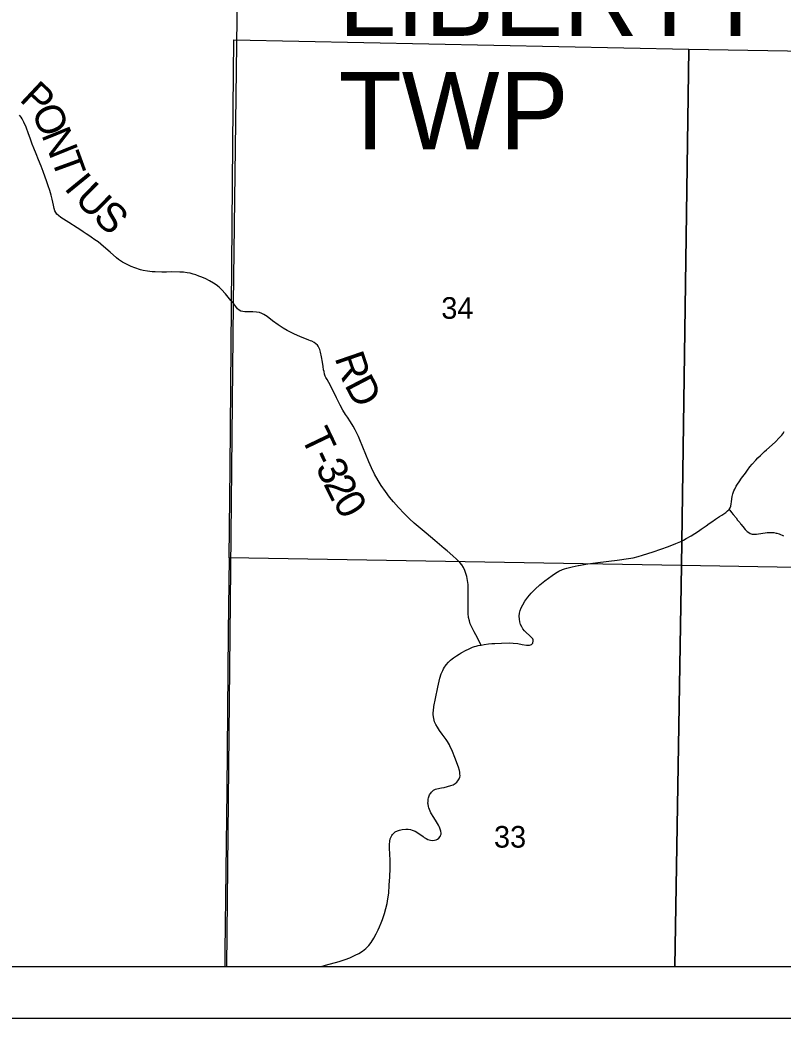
# Model space of a CAD drawing. Extents: x 0 to 34, y 0 to 22.
# Drawn here: x 6.032 to 7.51, y 14 to 15.933 of the extents above; entities that cross this region are included whole.
import ezdxf

# ---------------------------------------------------------------- set-up
doc = ezdxf.new("R2010")
doc.units = 0
for name, color, linetype in [('GM_X_Corporation', 7, 'Continuous'), ('GM_X_County_Road', 7, 'Continuous'), ('GM_X_Section_Text', 7, 'Continuous'), ('GM_X_Township_Road', 7, 'Continuous'), ('GM_X_Township_Road_Text', 7, 'Continuous'), ('GM_X_Township_Text', 7, 'Continuous'), ('SH_Data', 7, 'Continuous'), ('SH_Text', 7, 'Continuous')]:
    doc.layers.add(name, color=color, linetype=linetype)

msp = doc.modelspace()

# ---------------------------------------------------------------- linework, layer by layer
at = {"layer": 'GM_X_Corporation'}
msp.add_lwpolyline([(2.1, 19.4241), (2.1, 14.1), (8.9, 14.1), (8.9, 16.8499)], dxfattribs=at)
for points in [[(7.3273, 15.8762), (7.3131, 14.8764), (6.4376, 14.8914), (6.439, 15.0647), (6.4418, 15.3781), (6.4444, 15.6936), (6.4463, 15.8942)], [(8.3203, 15.8594), (8.313, 14.8592), (7.3131, 14.8764), (7.3273, 15.8762)], [(6.4289, 14.1), (7.3003, 14.1), (7.3131, 14.8764), (6.4376, 14.8914), (6.4356, 14.7473), (6.4329, 14.4414), (6.4292, 14.1288)], [(7.3003, 14.1), (8.305, 14.1), (8.313, 14.8592), (7.3131, 14.8764)]]:
    msp.add_lwpolyline(points, close=True, dxfattribs=at)
at = {"layer": 'GM_X_County_Road'}
for points in [[(7.4055, 14.985), (7.4074, 14.988), (7.4087, 14.9912), (7.4096, 14.9959), (7.41, 14.9996), (7.4107, 15.0052), (7.4115, 15.0101), (7.4128, 15.015), (7.4149, 15.0209), (7.4164, 15.0244), (7.4195, 15.0299), (7.4221, 15.0341), (7.4249, 15.0383), (7.4298, 15.0454), (7.4371, 15.0555), (7.4411, 15.0607), (7.446, 15.0674), (7.4504, 15.0727), (7.4571, 15.0801), (7.4613, 15.0847), (7.4663, 15.0894), (7.4704, 15.0936), (7.4743, 15.097), (7.4781, 15.1004), (7.4947, 15.1155), (7.5035, 15.1241), (7.5076, 15.1287), (7.5098, 15.1316), (7.5123, 15.1357)], [(6.9251, 14.7224), (6.9309, 14.7237), (6.9396, 14.7247), (6.9463, 14.7253), (6.952, 14.7254), (6.9645, 14.7258), (6.9794, 14.7263), (6.9874, 14.726), (6.9961, 14.7252), (7.0047, 14.7237), (7.0132, 14.7221), (7.0156, 14.7219), (7.0174, 14.7219), (7.0191, 14.7222), (7.0211, 14.7227), (7.0228, 14.7237), (7.0252, 14.726), (7.0256, 14.7269), (7.0264, 14.7296), (7.026, 14.7322), (7.0252, 14.7342), (7.0236, 14.7366), (7.0192, 14.7408), (7.0125, 14.7465), (7.0094, 14.7497), (7.0063, 14.7536), (7.0039, 14.7574), (7.0017, 14.762), (7.0002, 14.7675), (6.9995, 14.7725), (6.9993, 14.7782), (6.9999, 14.7839), (7.0011, 14.7895), (7.0028, 14.7943), (7.0058, 14.8005), (7.0101, 14.8074), (7.0157, 14.815), (7.0222, 14.8225), (7.0301, 14.8306), (7.0393, 14.839), (7.0485, 14.8464), (7.0629, 14.8571), (7.0691, 14.8613), (7.0761, 14.8655), (7.083, 14.8686), (7.087, 14.8702), (7.0916, 14.8715), (7.0964, 14.8728), (7.1016, 14.8739), (7.113, 14.8762), (7.1138, 14.8764), (7.1322, 14.8796), (7.1513, 14.8823), (7.1889, 14.887), (7.211, 14.8898), (7.2201, 14.8915), (7.2292, 14.8936), (7.2381, 14.8961), (7.2586, 14.9031), (7.288, 14.9134), (7.3024, 14.9188), (7.3121, 14.923), (7.3176, 14.9256), (7.3225, 14.9284), (7.3321, 14.934), (7.3461, 14.9432), (7.3512, 14.9468), (7.3553, 14.9495), (7.3611, 14.9535), (7.367, 14.9577), (7.3722, 14.9611), (7.3793, 14.966), (7.3871, 14.9711), (7.3918, 14.9741), (7.399, 14.9789), (7.4027, 14.982), (7.4055, 14.985)], [(7.4055, 14.985), (7.4071, 14.9833), (7.4105, 14.979), (7.4138, 14.9749), (7.419, 14.9684), (7.422, 14.9645), (7.4261, 14.9595), (7.4277, 14.957), (7.4284, 14.9563)], [(7.4284, 14.9563), (7.4322, 14.9517), (7.4369, 14.9461), (7.4408, 14.9422), (7.4436, 14.94), (7.4466, 14.9383), (7.4483, 14.9376), (7.45, 14.9373), (7.4518, 14.9371), (7.4542, 14.937), (7.4584, 14.9373), (7.4794, 14.9401), (7.4863, 14.9405), (7.492, 14.9401), (7.4969, 14.9392), (7.4978, 14.939)], [(7.4978, 14.939), (7.5024, 14.9376), (7.5111, 14.9341)], [(6.8328, 14.5951), (6.8338, 14.6032), (6.8367, 14.6191), (6.8413, 14.641), (6.8453, 14.658), (6.8479, 14.6664), (6.8509, 14.6733), (6.8524, 14.6765), (6.8543, 14.6794), (6.8562, 14.6822), (6.8575, 14.684), (6.8621, 14.6892), (6.866, 14.6929), (6.8693, 14.6956), (6.8717, 14.6973), (6.8778, 14.7017), (6.8825, 14.7048), (6.8867, 14.7074), (6.8966, 14.7127), (6.9006, 14.7146), (6.905, 14.7166), (6.9088, 14.7181), (6.9122, 14.7192), (6.9158, 14.7204), (6.9196, 14.7215), (6.9251, 14.7224)], [(6.6158, 14.1), (6.624, 14.1022), (6.6503, 14.1093), (6.6621, 14.1131), (6.6713, 14.1168), (6.6814, 14.1215), (6.6885, 14.1252), (6.6953, 14.1294), (6.7021, 14.1346), (6.7077, 14.1402), (6.7126, 14.1465), (6.7177, 14.1549), (6.7219, 14.1631), (6.7261, 14.1711), (6.7285, 14.1764), (6.7318, 14.1841), (6.7341, 14.191), (6.7382, 14.2027), (6.741, 14.2122), (6.7433, 14.2218), (6.7449, 14.2309), (6.7463, 14.2419), (6.7475, 14.2574), (6.7484, 14.2735), (6.749, 14.2896), (6.749, 14.3057), (6.7485, 14.3175), (6.7478, 14.3287), (6.7478, 14.3363), (6.7484, 14.3426), (6.7494, 14.3469), (6.7509, 14.3511), (6.7522, 14.3533), (6.7535, 14.3555), (6.7562, 14.3583), (6.7586, 14.3604), (6.7632, 14.3628), (6.7675, 14.3641), (6.7725, 14.365), (6.7795, 14.3655), (6.7843, 14.3656), (6.7887, 14.365), (6.792, 14.364), (6.7973, 14.3618), (6.8005, 14.36), (6.8032, 14.3582), (6.8083, 14.3545), (6.8129, 14.3513), (6.8153, 14.3495), (6.8186, 14.3478), (6.8224, 14.346), (6.827, 14.3445), (6.8318, 14.3439), (6.8353, 14.3444), (6.8381, 14.3452), (6.8408, 14.3464), (6.8431, 14.3482), (6.8458, 14.3513), (6.8467, 14.3534), (6.8476, 14.356), (6.8479, 14.358), (6.8474, 14.3617), (6.8467, 14.3641), (6.8454, 14.3676), (6.8441, 14.3707), (6.8426, 14.3737), (6.841, 14.377), (6.8391, 14.3802), (6.8338, 14.3885), (6.8282, 14.3976), (6.8266, 14.4008), (6.8252, 14.4038), (6.8242, 14.4068), (6.8233, 14.4098), (6.8226, 14.4142), (6.8224, 14.4163), (6.8225, 14.4192), (6.823, 14.4237), (6.8234, 14.4262), (6.8242, 14.4286), (6.8256, 14.4322), (6.8267, 14.4342), (6.8277, 14.4356), (6.8291, 14.4375), (6.831, 14.4393), (6.8332, 14.441), (6.8354, 14.4423), (6.8372, 14.443), (6.8393, 14.4437), (6.8485, 14.4458), (6.8537, 14.4466), (6.8602, 14.4481), (6.8666, 14.45), (6.8711, 14.4519), (6.8753, 14.4543), (6.8785, 14.457), (6.8805, 14.4591), (6.8818, 14.4611), (6.8829, 14.4631), (6.8839, 14.4664), (6.8844, 14.4693), (6.8843, 14.4727), (6.8839, 14.4764), (6.8833, 14.4794), (6.8814, 14.4858), (6.8743, 14.5044), (6.8698, 14.516), (6.8677, 14.5208), (6.8656, 14.5255), (6.8639, 14.5288), (6.862, 14.532), (6.8599, 14.5356), (6.8574, 14.5393), (6.8499, 14.5499), (6.8448, 14.557), (6.8406, 14.5632), (6.8378, 14.5682), (6.8364, 14.5709), (6.8353, 14.5739), (6.8343, 14.5769), (6.8335, 14.58), (6.833, 14.5834), (6.8326, 14.5876), (6.8325, 14.5916), (6.8328, 14.5951)]]:
    msp.add_lwpolyline(points, dxfattribs=at)
at = {"layer": 'GM_X_Township_Road'}
for points in [[(6.4461, 15.3829), (6.4454, 15.3838), (6.4408, 15.3898), (6.43, 15.4025), (6.4222, 15.4112), (6.4177, 15.4154), (6.4118, 15.42), (6.4071, 15.4231), (6.3991, 15.4279), (6.392, 15.4316), (6.3842, 15.4349), (6.3788, 15.437), (6.3727, 15.4393), (6.3678, 15.4408), (6.3619, 15.4424), (6.3557, 15.4435), (6.349, 15.4444), (6.3416, 15.4447), (6.3261, 15.4449), (6.3156, 15.4445), (6.307, 15.4445), (6.2942, 15.445), (6.2882, 15.4454), (6.2793, 15.4463), (6.2708, 15.4478), (6.2654, 15.4492), (6.2548, 15.4527), (6.2474, 15.4557), (6.2384, 15.4598), (6.2307, 15.4639), (6.2266, 15.4666), (6.2231, 15.4691), (6.2192, 15.4723), (6.2067, 15.4835), (6.1941, 15.4945), (6.1834, 15.5031), (6.1774, 15.5074), (6.1702, 15.5121), (6.1653, 15.5154), (6.1602, 15.5189), (6.1544, 15.5227), (6.1482, 15.527), (6.1431, 15.5301), (6.1266, 15.5406), (6.111, 15.5506), (6.1066, 15.554), (6.1038, 15.5565), (6.1013, 15.56), (6.0999, 15.5634), (6.0985, 15.5676), (6.0971, 15.5742), (6.0942, 15.5858), (6.0924, 15.5938), (6.0897, 15.6027), (6.087, 15.6119), (6.0843, 15.6193), (6.0773, 15.6392), (6.0733, 15.6496), (6.0679, 15.6621), (6.0632, 15.6734), (6.0587, 15.6846), (6.0558, 15.6927), (6.0519, 15.7039), (6.0489, 15.7127), (6.0439, 15.7253), (6.0396, 15.7348), (6.0362, 15.7416), (6.0341, 15.7446), (6.0311, 15.7485)], [(6.9251, 14.7224), (6.9223, 14.7282), (6.9185, 14.736), (6.9118, 14.7478), (6.9071, 14.7572), (6.9044, 14.7635), (6.9025, 14.7694), (6.9011, 14.776), (6.9004, 14.7834), (6.9, 14.7945), (6.9004, 14.8286), (6.8999, 14.8398), (6.899, 14.8471), (6.8976, 14.8551), (6.896, 14.8611), (6.8938, 14.8669), (6.891, 14.8724), (6.8877, 14.8777), (6.8838, 14.8825), (6.8778, 14.8888), (6.8704, 14.8954), (6.8594, 14.9045), (6.8536, 14.9092), (6.8357, 14.9245), (6.8187, 14.9391), (6.7954, 14.9586), (6.7863, 14.967), (6.7761, 14.977), (6.7652, 14.9888), (6.7558, 14.9994), (6.748, 15.009), (6.7398, 15.0199), (6.7316, 15.0316), (6.7256, 15.041), (6.7187, 15.0535), (6.713, 15.0653), (6.708, 15.0773), (6.6903, 15.1196), (6.6876, 15.1262), (6.6846, 15.1328), (6.6812, 15.1394), (6.6772, 15.1464), (6.672, 15.1549), (6.6663, 15.1638), (6.6629, 15.169), (6.6577, 15.1775), (6.6525, 15.1866), (6.645, 15.201), (6.6334, 15.225), (6.6268, 15.2367), (6.6248, 15.2402), (6.6234, 15.243), (6.6222, 15.2467), (6.621, 15.252), (6.6201, 15.2556), (6.6192, 15.2617), (6.6181, 15.2703), (6.6162, 15.2807), (6.614, 15.2898), (6.6126, 15.2946), (6.6111, 15.2984), (6.6096, 15.3011), (6.6081, 15.3033), (6.6054, 15.3059), (6.6019, 15.3084), (6.5975, 15.3107), (6.5951, 15.3117), (6.5917, 15.313), (6.5837, 15.3159), (6.5757, 15.3191), (6.5627, 15.3249), (6.5494, 15.3315), (6.5419, 15.3358), (6.5321, 15.3424), (6.5211, 15.3505), (6.5107, 15.3584), (6.5046, 15.3626), (6.5007, 15.3645), (6.496, 15.3661), (6.49, 15.3672), (6.4832, 15.3679), (6.4758, 15.3678), (6.4678, 15.3676), (6.4635, 15.368), (6.46, 15.3691), (6.4568, 15.3709), (6.4535, 15.3737), (6.4499, 15.3779), (6.4461, 15.3829)]]:
    msp.add_lwpolyline(points, dxfattribs=at)
at = {"layer": 'GM_X_Township_Text'}
msp.add_lwpolyline([(6.4571, 16.891), (6.446, 16.7493), (6.4489, 16.4198), (6.4561, 16.2366), (6.4452, 15.3843), (6.4323, 14.1), (8.9, 14.1), (8.9, 16.8499)], dxfattribs=at)
at = {"layer": 'SH_Data'}
for p, q in [((2.1, 14.1), (8.9, 14.1)), ((2, 14), (9, 14))]:
    msp.add_line(p, q, dxfattribs=at)
at = {"layer": 'SH_Text'}
msp.add_lwpolyline([(2.1, 16.074), (2.1, 14.1), (6.4323, 14.1)], dxfattribs=at)

# ---------------------------------------------------------------- texts
at = {"layer": 'GM_X_Section_Text'}
for s, p in [('34', (6.8482, 15.3542)), ('33', (6.9502, 14.33))]:
    msp.add_text(s, height=0.04186, rotation=0, dxfattribs=at).set_placement(p)
at = {"layer": 'GM_X_Township_Road_Text'}
for s, rotation, p in [('P', 316.7978, (6.0292, 15.7777)), ('O', 292.7992, (6.0536, 15.7566)), ('N', 292.0429, (6.0729, 15.7107)), ('T', 289.9882, (6.0915, 15.6649)), ('I', 309.2078, (6.1162, 15.6069)), ('U', 315.5616, (6.1356, 15.5837)), ('S', 315.9637, (6.1716, 15.5484)), ('R', 288.8916, (6.6411, 15.2789)), ('D', 297.561, (6.6598, 15.2263)), ('T', 295.6163, (6.5751, 15.1264)), ('3', 295.766, (6.6037, 15.0669)), ('-', 295.6514, (6.5935, 15.088)), ('2', 296.2976, (6.6192, 15.0348)), ('0', 300.5873, (6.6369, 14.9994))]:
    msp.add_text(s, height=0.0568, rotation=rotation, dxfattribs=at).set_placement(p)
at = {"layer": 'GM_X_Township_Text'}
for s, p in [('LIBERTY', (6.6491, 15.9021)), ('TWP', (6.6491, 15.6821))]:
    msp.add_text(s, height=0.15, rotation=0, dxfattribs=at).set_placement(p)

doc.saveas('drawing.dxf')
